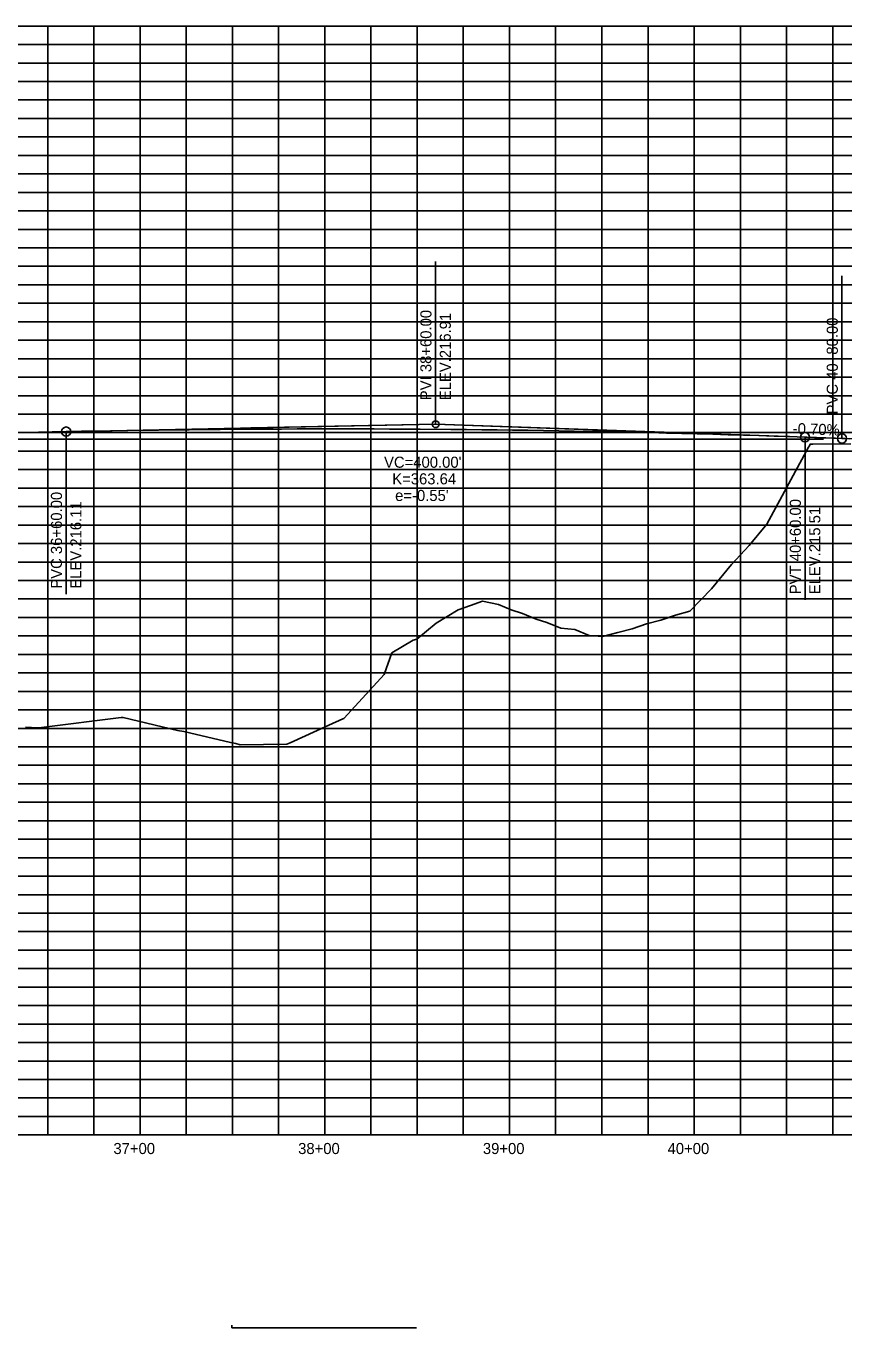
# Model space of a CAD drawing. Extents: x 1732967 to 1742744, y 374025 to 374739.
# Drawn here: x 1741552 to 1741995, y 374025 to 374730 of the extents above; entities that cross this region are included whole.
import ezdxf

# ---------------------------------------------------------------- set-up
doc = ezdxf.new("R2010")
doc.units = 0
for name, color, linetype in [('Level 8', 7, 'Continuous'), ('R_Axis_Annotation', 7, 'Continuous'), ('R_Exist Surface', 7, 'Continuous'), ('R_Grid', 7, 'Continuous'), ('R_Grid_Minor', 7, 'Continuous'), ('R_Horz Alg', 7, 'Continuous'), ('R_Vert Alg', 7, 'Continuous'), ('R_Vert Alg Annot', 7, 'Continuous')]:
    doc.layers.add(name, color=color, linetype=linetype)

msp = doc.modelspace()

# ---------------------------------------------------------------- linework, layer by layer
at = {"layer": 'Level 8'}
msp.add_line((1741428.91, 374506.11), (1741983.91, 374506.11), dxfattribs=at)
at = {"layer": 'R_Exist Surface'}
msp.add_lwpolyline([(1741551.93, 374350.3), (1741558.51, 374349.94), (1741560.56, 374350.09), (1741603.66, 374355.4), (1741604.74, 374355.49), (1741634.26, 374348.47), (1741637.68, 374347.85), (1741662.82, 374342), (1741665.84, 374341.32), (1741668.13, 374340.75), (1741693.29, 374340.97), (1741695.18, 374341.78), (1741716.18, 374351.29), (1741723.68, 374354.67), (1741724.18, 374354.92), (1741724.48, 374355.15), (1741746.07, 374378.79), (1741750.14, 374390.38), (1741761.7, 374397.37), (1741763.71, 374397.79), (1741774.21, 374406.47), (1741786.13, 374413.69), (1741792.72, 374416.1), (1741799.23, 374418.48), (1741807.91, 374416.61), (1741814.91, 374413.69), (1741820.97, 374411.81), (1741828.3, 374408.75), (1741834.04, 374406.95), (1741841.67, 374403.74), (1741849.22, 374403.16), (1741857, 374399.8), (1741864.23, 374399.23), (1741872.56, 374401.42), (1741880.29, 374403.44), (1741888.14, 374406.12), (1741895.85, 374408.17), (1741903.79, 374410.86), (1741911.49, 374412.94), (1741923.19, 374425.14), (1741934.02, 374438.28), (1741943.61, 374448.52), (1741953.17, 374460.03), (1741975.8, 374501.79), (1741976.41, 374502.39), (1741976.68, 374503.31), (1741978.17, 374503.33), (1741998.74, 374503.59)], dxfattribs=at)
at = {"layer": 'R_Grid'}
for p, q in [((1739913.91, 374729.61), (1742713.91, 374729.61)), ((1741613.91, 374129.61), (1741613.91, 374729.61)), ((1741713.91, 374129.61), (1741713.91, 374729.61)), ((1741813.91, 374129.61), (1741813.91, 374729.61)), ((1741913.91, 374129.61), (1741913.91, 374729.61)), ((1739913.91, 374679.61), (1742713.91, 374679.61)), ((1739913.91, 374629.61), (1742713.91, 374629.61)), ((1739913.91, 374579.61), (1742713.91, 374579.61)), ((1739913.91, 374529.61), (1742713.91, 374529.61)), ((1739913.91, 374479.61), (1742713.91, 374479.61)), ((1739913.91, 374429.61), (1742713.91, 374429.61)), ((1739913.91, 374379.61), (1742713.91, 374379.61)), ((1739913.91, 374329.61), (1742713.91, 374329.61)), ((1739913.91, 374279.61), (1742713.91, 374279.61)), ((1739913.91, 374229.61), (1742713.91, 374229.61)), ((1739913.91, 374179.61), (1742713.91, 374179.61)), ((1739913.91, 374129.61), (1742713.91, 374129.61))]:
    msp.add_line(p, q, dxfattribs=at)
at = {"layer": 'R_Grid_Minor'}
for p, q in [((1741563.91, 374129.61), (1741563.91, 374729.61)), ((1741588.91, 374129.61), (1741588.91, 374729.61)), ((1741638.91, 374129.61), (1741638.91, 374729.61)), ((1741663.91, 374129.61), (1741663.91, 374729.61)), ((1741688.91, 374129.61), (1741688.91, 374729.61)), ((1741738.91, 374129.61), (1741738.91, 374729.61)), ((1741763.91, 374129.61), (1741763.91, 374729.61)), ((1741788.91, 374129.61), (1741788.91, 374729.61)), ((1741838.91, 374129.61), (1741838.91, 374729.61)), ((1741863.91, 374129.61), (1741863.91, 374729.61)), ((1741888.91, 374129.61), (1741888.91, 374729.61)), ((1741938.91, 374129.61), (1741938.91, 374729.61)), ((1741963.91, 374129.61), (1741963.91, 374729.61)), ((1741988.91, 374129.61), (1741988.91, 374729.61)), ((1739913.91, 374719.61), (1742713.91, 374719.61)), ((1739913.91, 374709.61), (1742713.91, 374709.61)), ((1739913.91, 374699.61), (1742713.91, 374699.61)), ((1739913.91, 374689.61), (1742713.91, 374689.61)), ((1739913.91, 374669.61), (1742713.91, 374669.61)), ((1739913.91, 374659.61), (1742713.91, 374659.61)), ((1739913.91, 374649.61), (1742713.91, 374649.61)), ((1739913.91, 374639.61), (1742713.91, 374639.61)), ((1739913.91, 374619.61), (1742713.91, 374619.61)), ((1739913.91, 374609.61), (1742713.91, 374609.61)), ((1739913.91, 374599.61), (1742713.91, 374599.61)), ((1739913.91, 374589.61), (1742713.91, 374589.61)), ((1739913.91, 374569.61), (1742713.91, 374569.61)), ((1739913.91, 374559.61), (1742713.91, 374559.61)), ((1739913.91, 374549.61), (1742713.91, 374549.61)), ((1739913.91, 374539.61), (1742713.91, 374539.61)), ((1739913.91, 374519.61), (1742713.91, 374519.61)), ((1739913.91, 374509.61), (1742713.91, 374509.61)), ((1739913.91, 374499.61), (1742713.91, 374499.61)), ((1739913.91, 374489.61), (1742713.91, 374489.61)), ((1739913.91, 374469.61), (1742713.91, 374469.61)), ((1739913.91, 374459.61), (1742713.91, 374459.61)), ((1739913.91, 374449.61), (1742713.91, 374449.61)), ((1739913.91, 374439.61), (1742713.91, 374439.61)), ((1739913.91, 374419.61), (1742713.91, 374419.61)), ((1739913.91, 374409.61), (1742713.91, 374409.61)), ((1739913.91, 374399.61), (1742713.91, 374399.61)), ((1739913.91, 374389.61), (1742713.91, 374389.61)), ((1739913.91, 374369.61), (1742713.91, 374369.61)), ((1739913.91, 374359.61), (1742713.91, 374359.61)), ((1739913.91, 374349.61), (1742713.91, 374349.61)), ((1739913.91, 374339.61), (1742713.91, 374339.61)), ((1739913.91, 374319.61), (1742713.91, 374319.61)), ((1739913.91, 374309.61), (1742713.91, 374309.61)), ((1739913.91, 374299.61), (1742713.91, 374299.61)), ((1739913.91, 374289.61), (1742713.91, 374289.61)), ((1739913.91, 374269.61), (1742713.91, 374269.61)), ((1739913.91, 374259.61), (1742713.91, 374259.61)), ((1739913.91, 374249.61), (1742713.91, 374249.61)), ((1739913.91, 374239.61), (1742713.91, 374239.61)), ((1739913.91, 374219.61), (1742713.91, 374219.61)), ((1739913.91, 374209.61), (1742713.91, 374209.61)), ((1739913.91, 374199.61), (1742713.91, 374199.61)), ((1739913.91, 374189.61), (1742713.91, 374189.61)), ((1739913.91, 374169.61), (1742713.91, 374169.61)), ((1739913.91, 374159.61), (1742713.91, 374159.61)), ((1739913.91, 374149.61), (1742713.91, 374149.61)), ((1739913.91, 374139.61), (1742713.91, 374139.61))]:
    msp.add_line(p, q, dxfattribs=at)
at = {"layer": 'R_Horz Alg'}
for p, q in [((1741313.91, 374504.96), (1741773.91, 374514.16)), ((1741313.91, 374504.96), (1741773.91, 374514.16)), ((1741413.91, 374506.96), (1741773.91, 374514.16)), ((1741773.91, 374514.16), (1742093.91, 374502.96)), ((1741773.91, 374514.16), (1742093.91, 374502.96)), ((1741773.91, 374514.16), (1742093.91, 374502.96)), ((1741413.91, 374506.96), (1741573.91, 374510.16)), ((1741413.91, 374506.96), (1741573.91, 374510.16)), ((1741973.91, 374507.16), (1741993.91, 374506.46)), ((1741973.91, 374507.16), (1741993.91, 374506.46))]:
    msp.add_line(p, q, dxfattribs=at)
for points in [[(1741573.91, 374510.16), (1741582.24, 374510.33), (1741590.58, 374510.48), (1741598.91, 374510.62), (1741607.24, 374510.75), (1741615.58, 374510.88), (1741623.91, 374510.99), (1741632.24, 374511.1), (1741640.58, 374511.19), (1741648.91, 374511.28), (1741657.24, 374511.35), (1741665.58, 374511.42), (1741673.91, 374511.48), (1741682.24, 374511.52), (1741690.58, 374511.56), (1741698.91, 374511.59), (1741707.24, 374511.61), (1741715.58, 374511.62), (1741723.91, 374511.62), (1741732.24, 374511.61), (1741740.58, 374511.59), (1741748.91, 374511.56), (1741757.24, 374511.52), (1741765.58, 374511.47), (1741782.24, 374511.35), (1741790.58, 374511.27), (1741798.91, 374511.18), (1741807.24, 374511.09), (1741815.58, 374510.98), (1741823.91, 374510.87), (1741832.24, 374510.74), (1741840.58, 374510.61), (1741848.91, 374510.46), (1741857.24, 374510.31), (1741865.58, 374510.15), (1741873.91, 374509.98), (1741882.24, 374509.79), (1741890.58, 374509.6), (1741898.91, 374509.4), (1741907.24, 374509.19), (1741915.58, 374508.97), (1741923.91, 374508.74), (1741932.24, 374508.5), (1741940.58, 374508.25), (1741948.91, 374508), (1741957.24, 374507.73), (1741965.58, 374507.45), (1741973.91, 374507.16)], [(1741573.91, 374510.16), (1741582.24, 374510.33), (1741590.58, 374510.48), (1741598.91, 374510.62), (1741607.24, 374510.75), (1741615.58, 374510.88), (1741623.91, 374510.99), (1741632.24, 374511.1), (1741640.58, 374511.19), (1741648.91, 374511.28), (1741657.24, 374511.35), (1741665.58, 374511.42), (1741673.91, 374511.48), (1741682.24, 374511.52), (1741690.58, 374511.56), (1741698.91, 374511.59), (1741707.24, 374511.61), (1741715.58, 374511.62), (1741723.91, 374511.62), (1741732.24, 374511.61), (1741740.58, 374511.59), (1741748.91, 374511.56), (1741757.24, 374511.52), (1741765.58, 374511.47), (1741782.24, 374511.35), (1741790.58, 374511.27), (1741798.91, 374511.18), (1741807.24, 374511.09), (1741815.58, 374510.98), (1741823.91, 374510.87), (1741832.24, 374510.74), (1741840.58, 374510.61), (1741848.91, 374510.46), (1741857.24, 374510.31), (1741865.58, 374510.15), (1741873.91, 374509.98), (1741882.24, 374509.79), (1741890.58, 374509.6), (1741898.91, 374509.4), (1741907.24, 374509.19), (1741915.58, 374508.97), (1741923.91, 374508.74), (1741932.24, 374508.5), (1741940.58, 374508.25), (1741948.91, 374508), (1741957.24, 374507.73), (1741965.58, 374507.45), (1741973.91, 374507.16)], [(1741993.91, 374506.46), (1741998.08, 374506.32)]]:
    msp.add_lwpolyline(points, dxfattribs=at)
at = {"layer": 'R_Vert Alg'}
for p, q in [((1741413.91, 374506.96), (1741573.91, 374510.16)), ((1741973.91, 374507.16), (1741993.91, 374506.46)), ((1741663.57, 374025.16), (1741663.57, 374026.66)), ((1741663.57, 374025.16), (1741763.57, 374025.16))]:
    msp.add_line(p, q, dxfattribs=at)
for points in [[(1741573.91, 374510.16), (1741582.24, 374510.33), (1741590.58, 374510.48), (1741598.91, 374510.62), (1741607.24, 374510.75), (1741615.58, 374510.88), (1741623.91, 374510.99), (1741632.24, 374511.1), (1741640.58, 374511.19), (1741648.91, 374511.28), (1741657.24, 374511.35), (1741665.58, 374511.42), (1741673.91, 374511.48), (1741682.24, 374511.52), (1741690.58, 374511.56), (1741698.91, 374511.59), (1741707.24, 374511.61), (1741715.58, 374511.62), (1741723.91, 374511.62), (1741732.24, 374511.61), (1741740.58, 374511.59), (1741748.91, 374511.56), (1741757.24, 374511.52), (1741765.58, 374511.47), (1741782.24, 374511.35), (1741790.58, 374511.27), (1741798.91, 374511.18), (1741807.24, 374511.09), (1741815.58, 374510.98), (1741823.91, 374510.87), (1741832.24, 374510.74), (1741840.58, 374510.61), (1741848.91, 374510.46), (1741857.24, 374510.31), (1741865.58, 374510.15), (1741873.91, 374509.98), (1741882.24, 374509.79), (1741890.58, 374509.6), (1741898.91, 374509.4), (1741907.24, 374509.19), (1741915.58, 374508.97), (1741923.91, 374508.74), (1741932.24, 374508.5), (1741940.58, 374508.25), (1741948.91, 374508), (1741957.24, 374507.73), (1741965.58, 374507.45), (1741973.91, 374507.16)], [(1741993.91, 374506.46), (1741998.08, 374506.32)]]:
    msp.add_lwpolyline(points, dxfattribs=at)
at = {"layer": 'R_Vert Alg Annot'}
for p, q in [((1741773.91, 374524.16), (1741773.91, 374602.16)), ((1741993.91, 374516.46), (1741993.91, 374594.46)), ((1741773.91, 374514.16), (1741773.91, 374524.16)), ((1741673.91, 374512.16), (1741773.91, 374514.16)), ((1741773.91, 374514.16), (1741873.91, 374510.66)), ((1741993.91, 374506.46), (1741993.91, 374516.46)), ((1741573.91, 374510.16), (1741573.91, 374500.16)), ((1741973.91, 374507.16), (1741973.91, 374497.16)), ((1741573.91, 374500.16), (1741573.91, 374422.16)), ((1741973.91, 374497.16), (1741973.91, 374419.16))]:
    msp.add_line(p, q, dxfattribs=at)
for centre, radius in [((1741773.91, 374514.16), 1.85), ((1741573.91, 374510.16), 2.5), ((1741973.91, 374507.16), 2.5), ((1741993.91, 374506.46), 2.5)]:
    msp.add_circle(centre, radius, dxfattribs=at)

# ---------------------------------------------------------------- texts
at = {"layer": 'R_Axis_Annotation'}
for s, p in [('37+00', (1741599.5, 374119.26)), ('38+00', (1741699.5, 374119.26)), ('39+00', (1741799.5, 374119.26)), ('40+00', (1741899.5, 374119.26))]:
    msp.add_text(s, height=6, dxfattribs=at).set_placement(p)
at = {"layer": 'R_Vert Alg Annot'}
for s, rotation, p in [('PVI 38+60.00', 90, (1741771.66, 374527.16)), ('ELEV.216.91', 90, (1741782.16, 374527.16)), ('PVC 40+80.00', 90, (1741991.66, 374519.46)), ('-0.70%', 357.99547, (1741967.17, 374508.9)), ('PVC 36+60.00', 90, (1741571.66, 374425.16)), ('ELEV.216.11', 90, (1741582.16, 374425.16)), ('PVT 40+60.00', 90, (1741971.66, 374422.16)), ('ELEV.215.51', 90, (1741982.16, 374422.16))]:
    msp.add_text(s, height=6, rotation=rotation, dxfattribs=at).set_placement(p)
for s, p in [("VC=400.00'", (1741746.01, 374490.61)), ('K=363.64', (1741750.44, 374481.61)), ("e=-0.55'", (1741752.01, 374472.61))]:
    msp.add_text(s, height=6, dxfattribs=at).set_placement(p)

doc.saveas('drawing.dxf')
